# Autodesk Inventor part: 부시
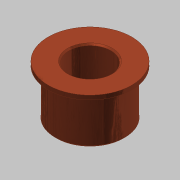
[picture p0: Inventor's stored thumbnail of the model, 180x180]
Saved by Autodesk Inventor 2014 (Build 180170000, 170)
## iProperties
Created: 2015-10
Part Number: 부시
Document SubType Name: Modeling
Designer: mdu
Density: 7.86 g/cm^3
Material: 강철, 연강
Mass: 246.97 g
Surface Area: 129.264 cm^2
Volume: 31.4212 cm^3
Appearance: Copper - Satin
Author: mdu
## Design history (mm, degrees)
sketch "스케치1"
  geometry: C1 r 31 at (0, 0) reference; C2 r 25 at (0, 0) reference; C3 r 30 at (0, 0) reference; 1 further point
  node "참조1"
  node "참조2"
  node "참조4"
extrude "돌출1" new body sketch "스케치1" distance "d0" = 3; taper "d1" = 0 deg
extrude "돌출2" join sketch "스케치1" distance "d2" = 36; taper "d3" = 0 deg
chamfer "모따기1" distance "d6" = 1; stored, may be unused: second distance "d7" = 2, angle "d8" = 45 deg
sketch "스케치3"
  geometry: C1 r 15 at (0, 0); 1 further point
  constraints: 1 centre point, 1 coincident
  dimensions: "d13" = 30 diameter of C1
extrude "돌출4" cut sketch "스케치3" stored distance "d14" = 10; taper "d15" = 0 deg
chamfer "모따기3" distance "d16" = 1; stored, may be unused: second distance "d17" = 2, angle "d18" = 45 deg
node "솔리드1"
